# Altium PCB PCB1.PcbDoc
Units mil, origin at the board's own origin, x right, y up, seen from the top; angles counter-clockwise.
Board outline 1535.43 x 2283.46 mil, 2 copper layers (Top Layer, Bottom Layer); 11 components, 21 nets, 78 pads, 13 vias.
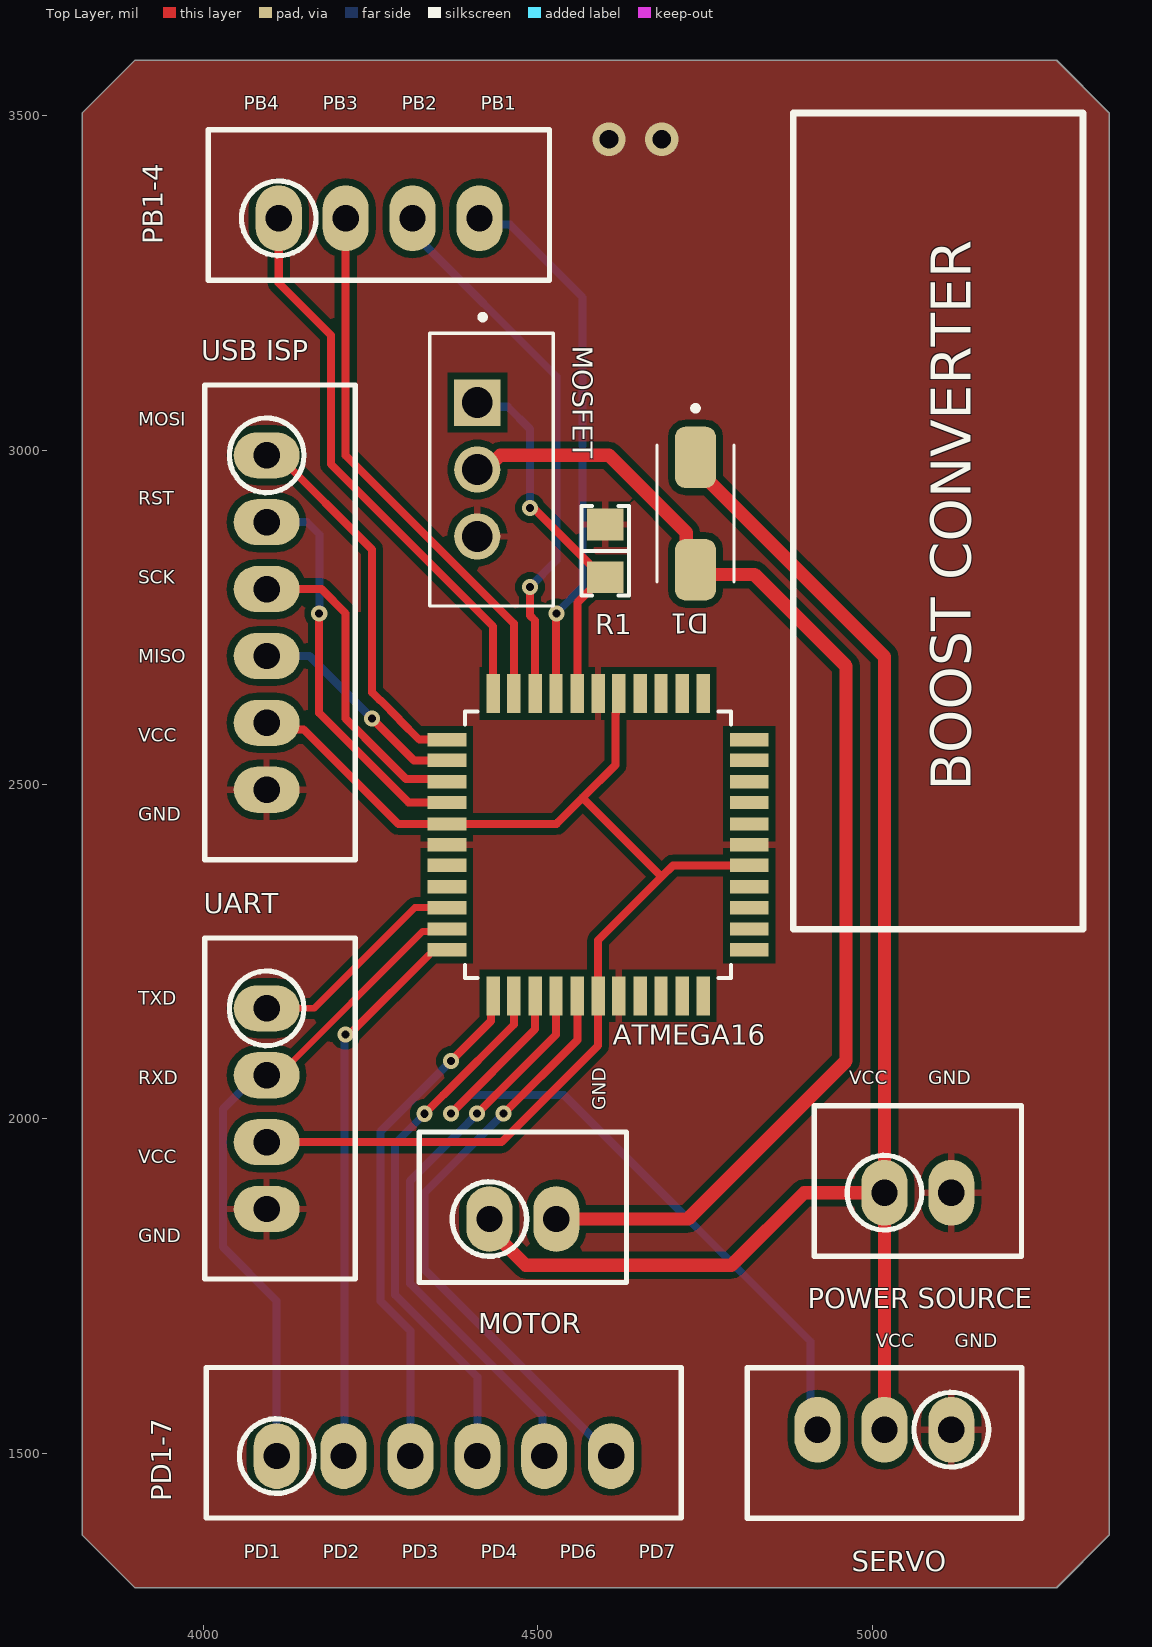
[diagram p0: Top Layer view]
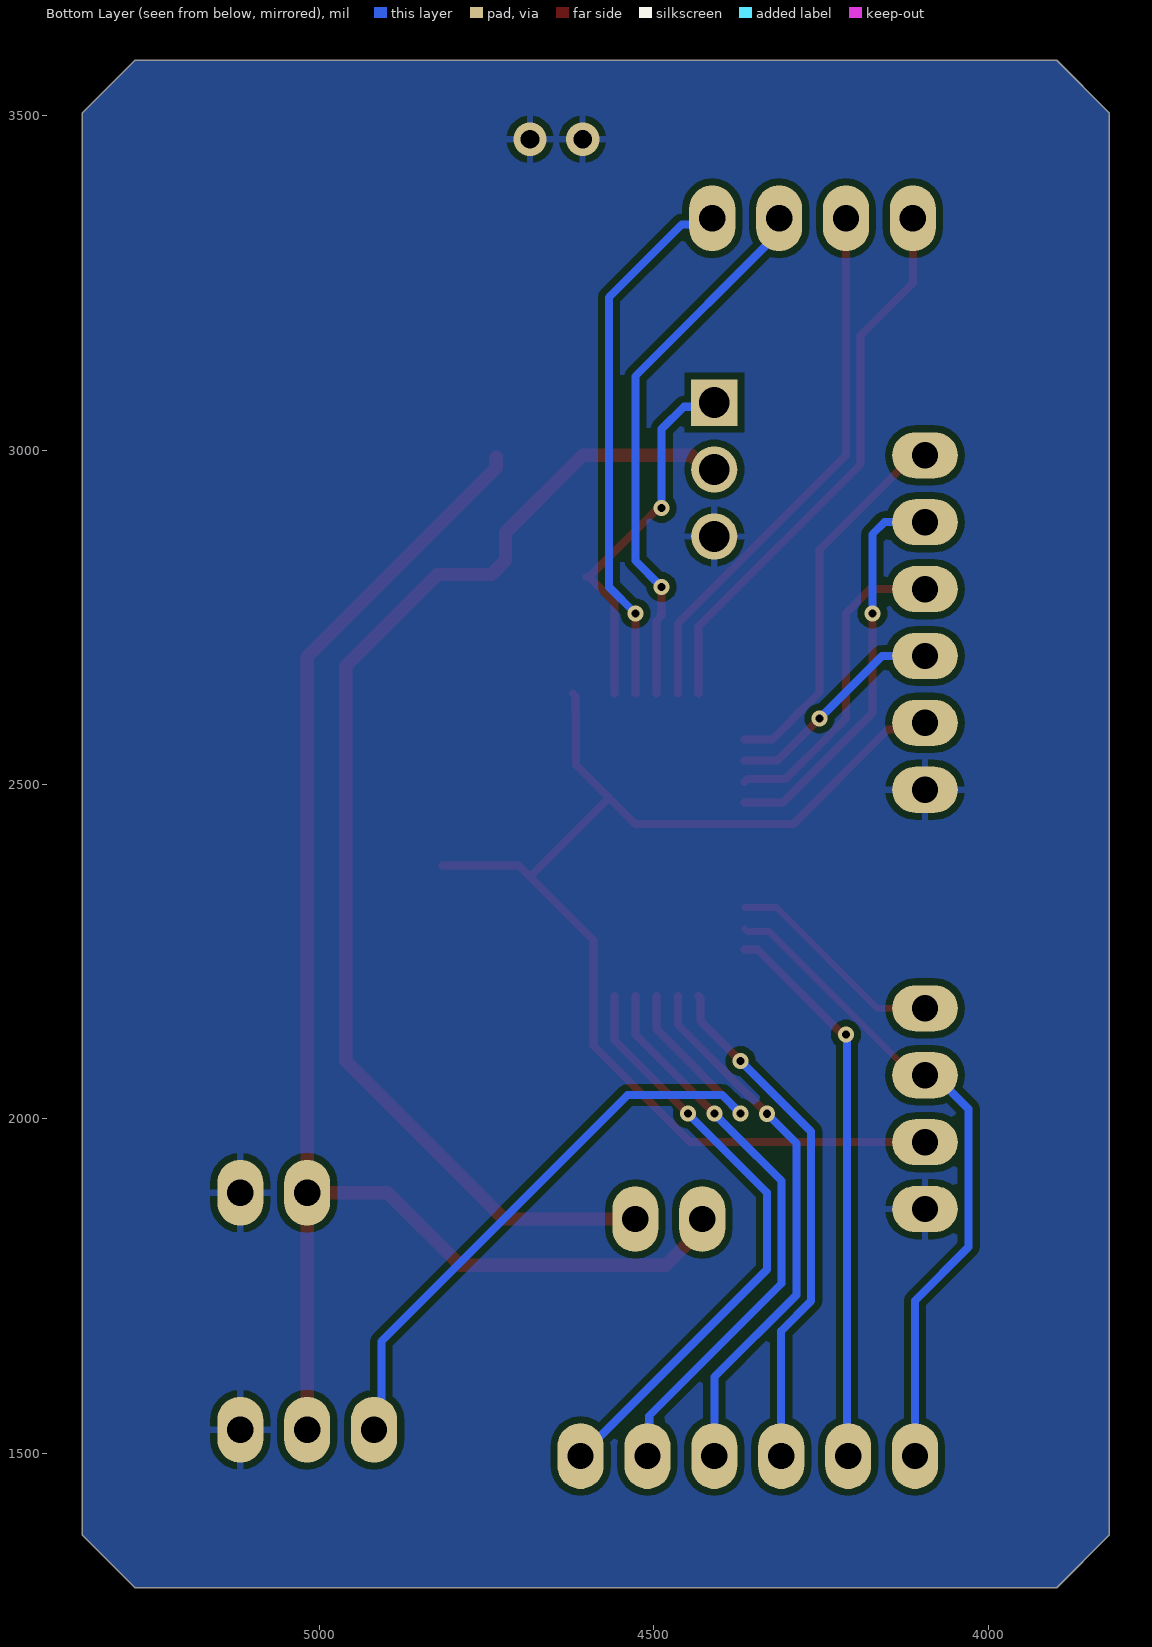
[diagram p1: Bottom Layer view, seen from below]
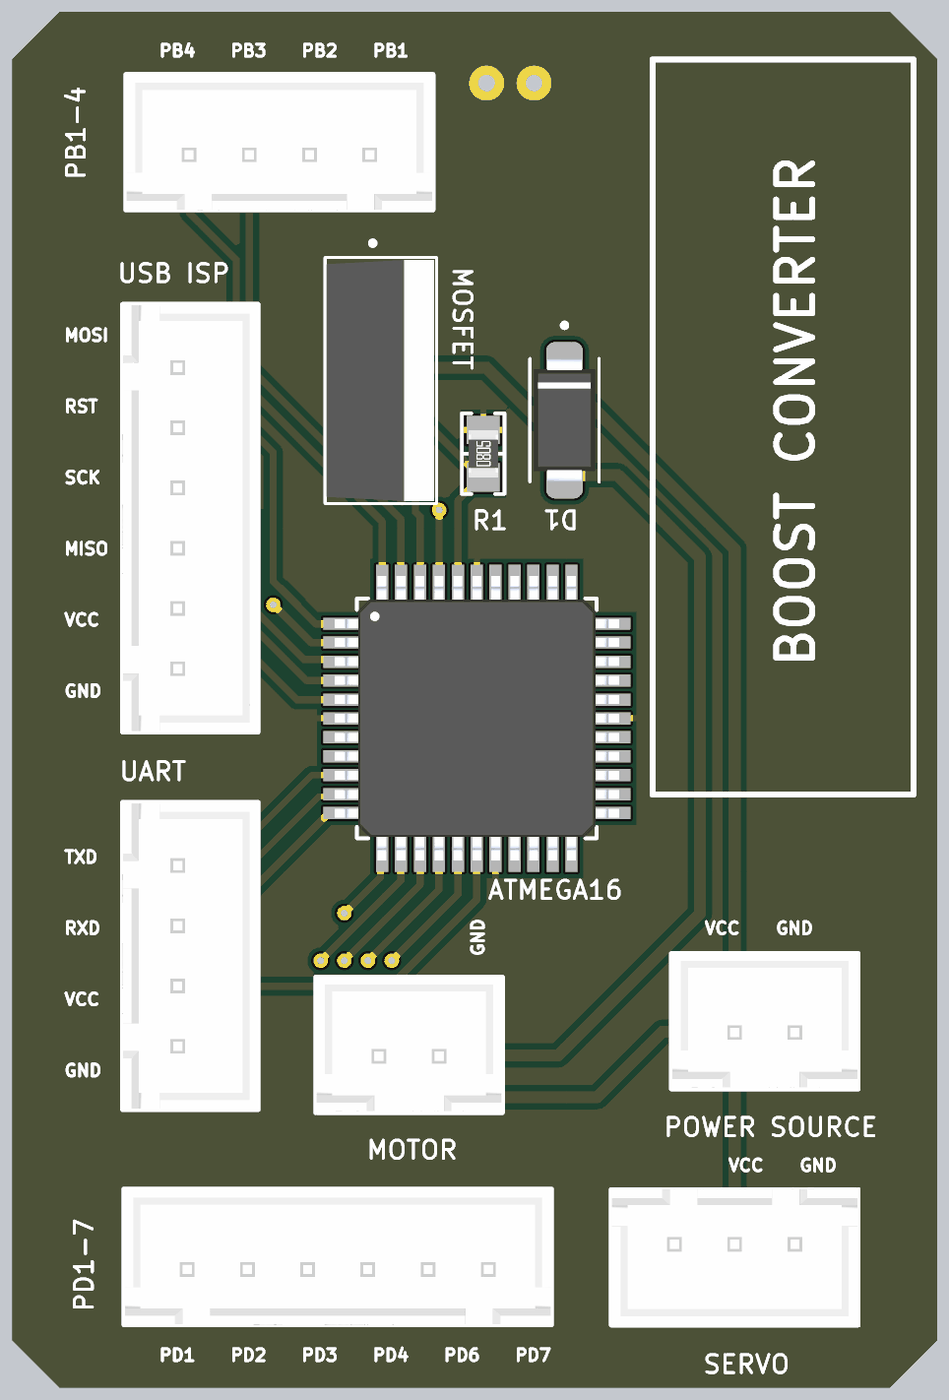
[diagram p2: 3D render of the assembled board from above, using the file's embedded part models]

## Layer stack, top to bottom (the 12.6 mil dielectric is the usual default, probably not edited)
Top Solder: solder mask 0.4, Solder Resist, Dk 3.5
Top Layer: signal copper 1.4
Dielectric 1: dielectric 12.6, FR-4, Dk 4.8
Bottom Layer: signal copper 1.4
Bottom Solder: solder mask 0.4, Solder Resist, Dk 3.5

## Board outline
3818.9,1377.95 3897.64,1299.21 5275.59,1299.21 5354.33,1377.95 5354.33,3503.94 5275.59,3582.68 4803.15,3582.68 3897.64,3582.68 3818.9,3503.94

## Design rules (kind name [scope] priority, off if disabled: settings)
Clearance [All] p1: gap=10 ignorepadtopadclearanceinfootprint=FALSE
PolygonConnect [All] p1: connectstyle=Relief reliefconductorwidth=10 reliefentries=4 polygonreliefangle="90 Angle" airgapwidth=10
RoutingVias [All] p1: holewidth=28 width=50 viastyle="Through Hole" minholewidth=12 minwidth=24 maxholewidth=28 maxwidth=50
SolderMaskExpansion [All] p1: expansion=4 istentingtop=FALSE
SupplyNets "Schematic Supply Nets" [InNet('GND')] p1: voltage=0.000
Width [All] p1: maxlimit=20 minlimit=7 preferedwidth=10
30 further rules are at their usual default settings.

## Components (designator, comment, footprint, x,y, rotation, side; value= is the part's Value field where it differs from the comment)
ATMEGA16 "ATMEGA16A-AUR" ATmega16_SMD 4590,2410 r0 top
D1 "Diode Schottky" "1N5824 SS54" 4735.63,2905 r270 top
MOSFET "FQP30N06L" TO-220 4409.45,2970.87 r270 top (schematic designator U1)
MOTOR "CN_JST_XH_2P_2.54MM" "JST XH 2P-H 2.54mm" 4477.37,1867.86 r180 top
PB1-4 "CN_JST_XH_4P_2.54MM" "JST XH 4P-H 2.54mm" 4262.32,3366.83 r180 top
PD1-7 "CN_JST_XH_6P_2.54MM" "JST XH 6P-H 2.54mm" 4359.17,1516.43 r180 top
"POWER SOURCE" "CN_JST_XH_2P_2.54MM" "JST XH 2P-H 2.54mm" 5067.92,1907.23 r180 top
R1 "10K_1%" "RES 0805_2012" 4600.63,2849.37 r90 top
SERVO "CN_JST_XH_3P_2.54MM" "JST XH 3P-H 2.54mm" 5018.39,1515.06 r0 top
UART "CN_JST_XH_4P_2.54MM" "JST XH 4P-H 2.54mm" 4114.86,2015.63 r90 top
"USB ISP" "CN_JST_XH_6P_2.54MM" "JST XH 6P-H 2.54mm" 4114.86,2742.4 r90 top

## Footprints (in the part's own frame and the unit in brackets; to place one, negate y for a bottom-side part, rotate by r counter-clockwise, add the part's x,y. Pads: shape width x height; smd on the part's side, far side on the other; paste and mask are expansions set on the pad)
"1N5824 SS54" [mm]
  rrect50% 2.33x1.55 smd: A(2.135,0) C(-2.135,0)
  silkscreen extent -4.1,-1.46 2.6,1.46, body extent -2.6,-1.3 2.6,1.3, height 2.4
ATmega16_SMD [mil]
  rect 58x20 smd paste+0 mask+4.02: 1(-226,157) 2(-226,126) 3(-226,94) 4(-226,63) 5(-226,31) 6(-226,0) 7(-226,-31) 8(-226,-63) 9(-226,-94) 10(-226,-126) 11(-226,-157) 23(226,-157) 24(226,-126) 25(226,-94) 26(226,-63) 27(226,-31) 28(226,0) 29(226,31) 30(226,63) 31(226,94) 32(226,126) 33(226,157)
  rect 20x58 smd paste+0 mask+4.02: 12(-157,-226) 13(-126,-226) 14(-94,-226) 15(-63,-226) 16(-31,-226) 17(0,-226) 18(31,-226) 19(63,-226) 20(94,-226) 21(126,-226) 22(157,-226) 34(157,226) 35(126,226) 36(94,226) 37(63,226) 38(31,226) 39(0,226) 40(-31,226) 41(-63,226) 42(-94,226) 43(-126,226) 44(-157,226)
  silkscreen extent -199,-199 199,199, body extent -236,-236 236,236, height 47
"JST XH 2P-H 2.54mm" [mm]
  oval 1.75x2.5 hole 1: 1(1.265,0.444) 2(-1.275,0.444)
  silkscreen extent -3.94,-2.86 3.93,2.86, body extent -3.9,-2.91 3.9,2.82, height 7
"JST XH 3P-H 2.54mm" [mm]
  oval 1.75x2.5 hole 1: 1(2.533,0.517) 2(-0.007,0.517) 3(-2.547,0.517)
  silkscreen extent -5.21,-2.85 5.2,2.87, body extent -5.18,-2.83 5.16,2.9, height 7
"JST XH 4P-H 2.54mm" [mm]
  oval 1.75x2.5 hole 1: 1(3.803,0.517) 2(1.263,0.517) 3(-1.277,0.517) 4(-3.817,0.517)
  silkscreen extent -6.48,-2.85 6.48,2.87, body extent -6.44,-2.85 6.44,2.88, height 7
"JST XH 6P-H 2.54mm" [mm]
  oval 1.75x2.5 hole 1: 1(6.343,0.517) 2(3.803,0.517) 3(1.263,0.517) 4(-1.277,0.517) 5(-3.817,0.517) 6(-6.357,0.517)
  silkscreen extent -9.02,-2.85 9.02,2.87, body extent -8.98,-2.85 8.98,2.88, height 7
"RES 0805_2012" [mm] "Chip Resistor, 2-Leads, Body 2.00x1.25mm, IPC Medium Density"
  rect 1.2x1.4 smd: 1(-1,0) 2(1,0)
  silkscreen extent -1.7,-0.9 1.7,0.9, body extent -1,-0.64 1,0.62, height 0.6
TO-220 [mm]
  rect 1.755x1.755 / inner round 1.755 / far side rect 1.755x1.755 hole 1.17: 1(-2.54,0)
  round 1.755 hole 1.17: 2(0,0) 3(2.54,0)
  silkscreen extent -5.89,-1.81 5.18,2.89, body extent -5.08,-1.76 5.08,2.79, height 19.65

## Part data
ATMEGA16: "AVR AVRÂ® ATmega Microcontroller IC 8-Bit 16MHz 16KB (8K x 16) FLASH 44-TQFP (10x10)", Package="TQFP-44 Microchip"
D1: library part "Diode Schottky 40 V 3A Surface Mount SMA"
MOSFET: library part MOSFET-30N06L_1, "No Description Available", Manufacturer_Name=onsemi
MOTOR "POWER SOURCE": "JST_XH_2P_2.54MM", Current Rating="3A AC/DC", Temperature range="-25 ~ +85", Voltage rating="250V AC/DC"
PB1-4 UART: "JST_XH_4P_2.54MM", Current Rating="3A AC/DC", Temperature range="-25 ~ +85", Voltage rating="250V AC/DC"
PD1-7 "USB ISP": "JST_XH_6P_2.54MM", Current Rating="3A AC/DC", Temperature range="-25 ~ +85", Voltage rating="250V AC/DC"
R1: library part RES_1%_0805_10K, "125mW Thick Film Resistors 150V ±100ppm/℃ ±1% 10kΩ 0805 Chip Resistor - Surface Mount ROHS", LCSC Part=C84376, Manufacturer=YAGEO, Mfr. Part=RC0805FR-0710KL, Package=0805
SERVO: "JST_XH_3P_2.54MM", Current Rating="3A AC/DC", Temperature range="-25 ~ +85", Voltage rating="250V AC/DC"

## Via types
v1: diameter 24, hole 12, Top Layer to Bottom Layer, 11 vias
v2: diameter 50, hole 28, Top Layer to Bottom Layer, 2 vias

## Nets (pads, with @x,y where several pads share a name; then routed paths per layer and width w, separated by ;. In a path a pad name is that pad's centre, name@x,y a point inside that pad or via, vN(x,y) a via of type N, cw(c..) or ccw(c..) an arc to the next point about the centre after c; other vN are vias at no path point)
GND: "POWER SOURCE.2" "USB ISP.6" ATMEGA16.6 ATMEGA16.18 ATMEGA16.28 ATMEGA16.39 MOSFET.3 R1.2 SERVO.1 UART.4
  other v2: 4606.3,3464.57 4685.04,3464.57
NetATMEGA16_1: "USB ISP.1" ATMEGA16.1 | length 571
  Top Layer w12: 4094.49,2992.13 4111,2992.13 4251.97,2851.16 4251.97,2637.8 4263.11,2626.65 4263.79,2626.65 4293.28,2597.17 4293.28,2596.48 4322.76,2567 ATMEGA16.1
NetATMEGA16_2: "USB ISP.4" ATMEGA16.2 | length 334.2
  Top Layer w12: v1(4252.2,2598.65) 4314.85,2536 ATMEGA16.2
  Bottom Layer w12: 4094.49,2692.12 4158.73,2692.12 v1(4252.2,2598.65)
NetATMEGA16_3: "USB ISP.3" ATMEGA16.3 | length 481.1
  Top Layer w12: 4094.49,2792.13 4176.37,2792.13 4212.6,2755.91 4212.6,2598.65 4240.6,2570.65 4240.6,2570.43 4303.02,2508 4360,2508 ATMEGA16.3
NetATMEGA16_4: "USB ISP.2" ATMEGA16.4 | length 599.8
  Top Layer w12: v1(4173.11,2755.79) 4173.11,2606.8 4306.91,2473 ATMEGA16.4
  Bottom Layer w12: 4094.49,2892.13 4155.12,2892.13 4173.23,2874.02 4173.23,2755.91 v1(4173.11,2755.79)
NetATMEGA16_5: "USB ISP.5" ATMEGA16.5 ATMEGA16.17 ATMEGA16.27 ATMEGA16.38 UART.3 | length 1881.7
  Top Layer w12: UART.3 4445.91,1965.36 4590,2109.46 ATMEGA16.17 4590,2267.17 4685.04,2362.2 ; 4094.49,2592.12 4104.12,2582.49 4149.8,2582.49 4291.28,2441 ATMEGA16.5 4527.61,2441 4530.31,2443.69 4566.93,2480.32 ; ATMEGA16.38 4617,2632 4617,2606.97 4616,2605.97 4616,2529.39 4566.93,2480.32 ; ATMEGA16.27 4701.83,2379 4685.04,2362.2 ; 4566.93,2480.32 4685.04,2362.2
NetATMEGA16_9: ATMEGA16.9 UART.1 | length 331.9
  Top Layer w10: UART.1 4165.41,2165.35 4316.05,2316 ATMEGA16.9
NetATMEGA16_10: ATMEGA16.10 PD1-7.1 UART.2 | length 998.2
  Top Layer w10: UART.2 4112.6,2065.35 4327.52,2280.27 4360.27,2280.27 ATMEGA16.10
  Bottom Layer w12: UART.2 4079.72,2065.35 4029.28,2014.91 4029.28,1808.39 4109.44,1728.23 PD1-7.1
NetATMEGA16_11: ATMEGA16.11 PD1-7.2 | length 835.2
  Top Layer w12: v1(4212.6,2125.98) 4214.89,2128.28 4220.28,2128.28 4345,2253 ATMEGA16.11
  Bottom Layer w12: PD1-7.2 4211.02,1497.64 4211.02,2124.41 v1(4212.6,2125.98)
NetATMEGA16_12: ATMEGA16.12 PD1-7.3 | length 776.2
  Top Layer w12: v1(4370.08,2086.61) 4430,2146.54 4430,2181 ATMEGA16.12
  Bottom Layer w12: PD1-7.3 4309.43,1683.08 4264.71,1727.8 4264.71,1981.24 v1(4370.08,2086.61)
NetATMEGA16_13: ATMEGA16.13 PD1-7.4 | length 812.5
  Top Layer w12: v1(4330.82,2007.76) 4330.82,2008.22 4358.48,2035.87 4358.94,2035.87 4464,2140.94 ATMEGA16.13
  Bottom Layer w12: v1(4330.82,2007.76) 4286.71,1963.65 4286.71,1736.91 4409.45,1614.17 PD1-7.4
NetATMEGA16_14: ATMEGA16.14 SERVO.3 | length 1066.5
  Top Layer w12: v1(4370.08,2007.87) 4370.08,2008.33 4496,2134.25 ATMEGA16.14
  Bottom Layer w12: v1(4370.08,2007.87) 4370.08,2008.33 4397.62,2035.87 4538.93,2035.87 4907.23,1667.57 4907.23,1546.32 SERVO.3
NetATMEGA16_15: ATMEGA16.15 PD1-7.5 | length 861.8
  Top Layer w12: v1(4409.22,2007.87) 4527.22,2125.88 4527.22,2183.78 ATMEGA16.15
  Bottom Layer w12: v1(4409.22,2007.87) 4409.22,2007.42 4381.68,1979.87 4381.45,1979.87 4308.71,1907.13 4308.71,1754.28 4506.75,1556.25 4506.75,1498.77 PD1-7.5
NetATMEGA16_16: ATMEGA16.16 PD1-7.6 | length 898
  Top Layer w12: v1(4448.82,2007.87) 4559,2118.06 ATMEGA16.16
  Bottom Layer w12: v1(4448.82,2007.87) 4330.71,1889.76 4330.71,1774.8 PD1-7.6
NetATMEGA16_40: ATMEGA16.40 MOSFET.1 R1.1 | length 558
  Top Layer w12: v1(4488.19,2913.39) 4490.48,2911.09 4495.6,2911.09 R1.1@4596.69,2810 ; ATMEGA16.40 4559,2772.31 R1.1@4596.69,2810 ; R1.1 R1.1@4596.69,2810
  Bottom Layer w12: MOSFET.1 4415.6,3064.72 4454.97,3064.72 4488.19,3031.5 v1(4488.19,2913.39)
NetATMEGA16_41: ATMEGA16.41 PB1-4.4 | length 812.1
  Top Layer w12: ATMEGA16.41 4527.28,2636.28 4527.28,2755.63 v1(4527.56,2755.91)
  Bottom Layer w12: PB1-4.4 4421.81,3337.25 4458.03,3337.25 4566.93,3228.35 4566.93,2795.28 v1(4527.56,2755.91)
NetATMEGA16_42: ATMEGA16.42 PB1-4.3 | length 819
  Top Layer w12: v1(4488.19,2795.28) 4488.19,2752.66 4496,2744.85 ATMEGA16.42
  Bottom Layer w12: PB1-4.3 4312.59,3325.2 4527.56,3110.24 4527.56,2834.65 v1(4488.19,2795.28)
NetATMEGA16_43: ATMEGA16.43 PB1-4.2 | length 814.6
  Top Layer w12: PB1-4.2 4212.6,2992.13 4464,2740.72 ATMEGA16.43
NetATMEGA16_44: ATMEGA16.44 PB1-4.1 | length 843.2
  Top Layer w12: PB1-4.1 4112.6,3249.61 4190.6,3171.61 4190.6,2978.88 4433,2736.48 ATMEGA16.44
NetD1_A: D1.A MOSFET.2 MOTOR.2 | length 1836.4
  Top Layer w20: MOSFET.2 4422.73,2970.87 4443.99,2992.13 4606.3,2992.13 4721.62,2876.8 4721.62,2834.95 4742.58,2814 4823.8,2814 4960.63,2677.17 4960.63,2086.61 4724.41,1850.39 MOTOR.2
NetD1_C: "POWER SOURCE.1" D1.C MOTOR.1 SERVO.2 | length 2243.5
  Top Layer w20: MOTOR.1 4427.56,1835.63 4482.01,1781.18 4789.4,1781.18 4897.98,1889.76 5018.11,1889.76 ; D1.C 4735.63,2973.7 5018.11,2691.22 5018.11,1889.76 ; SERVO.2 5018.11,1889.76
pads on no net: ATMEGA16.7 ATMEGA16.8 ATMEGA16.19 ATMEGA16.20 ATMEGA16.21 ATMEGA16.22 ATMEGA16.23 ATMEGA16.24 ATMEGA16.25 ATMEGA16.26 ATMEGA16.29 ATMEGA16.30 ATMEGA16.31 ATMEGA16.32 ATMEGA16.33 ATMEGA16.34 ATMEGA16.35 ATMEGA16.36 ATMEGA16.37

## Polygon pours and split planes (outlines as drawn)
GND on Top Layer "GND_L01_P000" (solid, remove dead copper, pour order 0): 3818.9,3503.94 3897.64,3582.68 5275.59,3582.68 5354.33,3503.94 5354.33,1377.95 5275.59,1299.21 3897.64,1299.21 3818.9,1377.95
GND on Bottom Layer "GND_L02_P001" (solid, remove dead copper, pour order 1): 3818.9,3503.94 3897.64,3582.68 5275.59,3582.68 5354.33,3503.94 5354.33,1377.95 5275.59,1299.21 3897.64,1299.21 3818.9,1377.95

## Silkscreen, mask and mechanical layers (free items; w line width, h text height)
Top Overlay:
  lines w10: 4881.89,2283.46 5314.96,2283.46 5314.96,3503.94 4881.89,3503.94 4881.89,2283.46
  text "PB4" at 4060.12,3508.94 h20
  text "PB3" at 4178.23,3508.94 h20
  text "PB2" at 4296.34,3508.94 h20
  text "PB1" at 4414.45,3508.94 h20
  text "MOSI" at 3902.64,3036.5 h20
  text "RST" at 3902.64,2918.39 h20
  text "SCK" at 3902.64,2800.28 h20
  text "MISO" at 3902.64,2682.17 h20
  text "VCC" at 3902.64,2564.06 h20
  text "BOOST CONVERTER" at 5147.48,2490.31 h60 r90
  text "GND" at 3902.64,2445.94 h20
  text "TXD" at 3902.64,2170.35 h20
  text "RXD" at 3902.64,2052.24 h20
  text "VCC" at 4965.63,2052.24 h20
  text "GND" at 5083.74,2052.24 h20
  text "GND" at 4601.3,2012.87 h20 r90
  text "VCC" at 3902.64,1934.13 h20
  text "GND" at 3902.64,1816.02 h20
  text "VCC" at 5005,1658.54 h20
  text "GND" at 5123.11,1658.54 h20
  text "PD1" at 4060.12,1343.58 h20
  text "PD2" at 4178.23,1343.58 h20
  text "PD3" at 4296.34,1343.58 h20
  text "PD4" at 4414.45,1343.58 h20
  text "PD6" at 4532.56,1343.58 h20
  text "PD7" at 4650.67,1343.58 h20
Mechanical 1:
  lines w10: 4803.15,3582.68 5275.59,3582.68 5354.33,3503.94 5354.33,1377.95 5275.59,1299.21 3897.64,1299.21 3818.9,1377.95 3818.9,3503.94 3897.64,3582.68 4803.15,3582.68 ; 4803.15,3582.68 4803.15,3582.68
